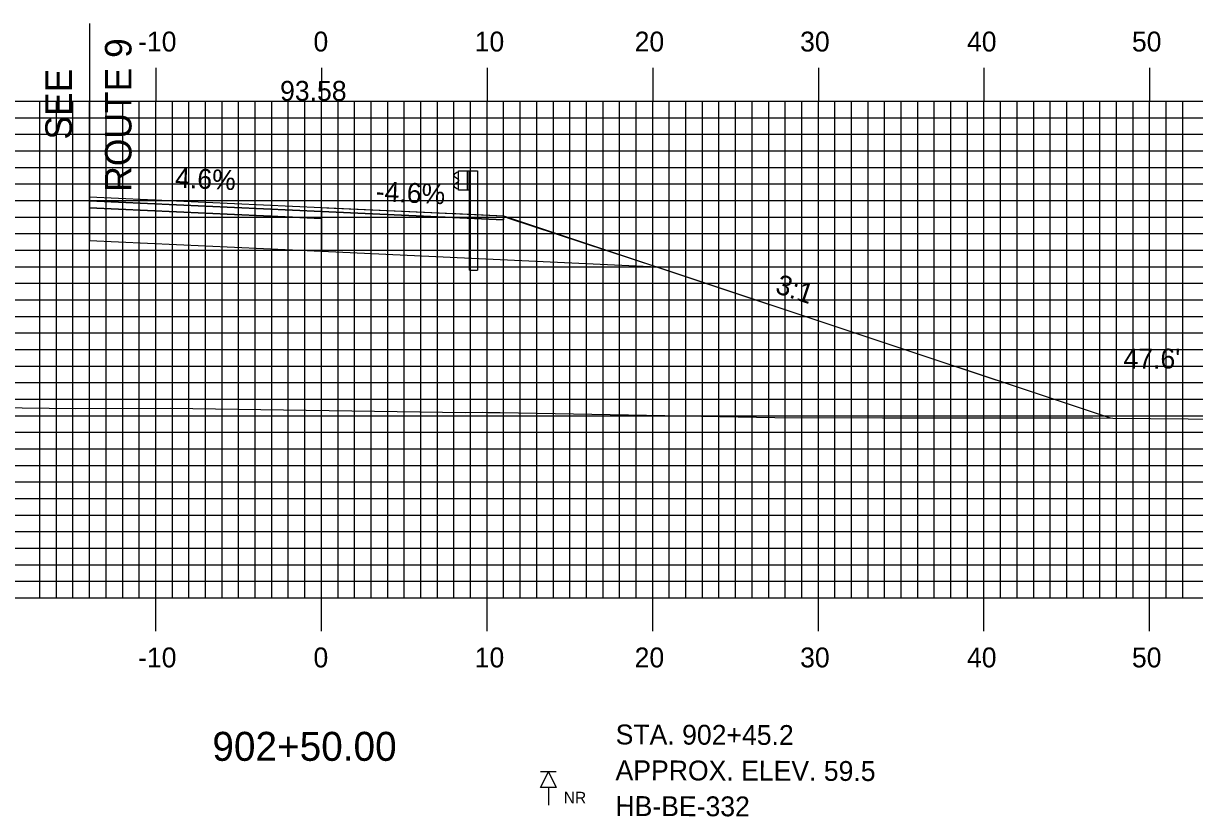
# Model space of a CAD drawing. Extents: x 856716 to 857060, y 364765 to 364985.
# Drawn here: x 856864.3 to 856935, y 364820.1 to 364868 of the extents above; entities that cross this region are included whole.
import ezdxf

# ---------------------------------------------------------------- set-up
doc = ezdxf.new("R2010")
doc.units = 0
for name, color, linetype in [('ANNOTATION', 7, 'Continuous'), ('BORING - NO REFUSAL', 7, 'Continuous'), ('D_Guardrail_Beam_Lt', 7, 'Continuous'), ('D_Roadway_Centerline', 7, 'Continuous'), ('D_Roadway_Centerline_Text', 7, 'Continuous'), ('D_Roadway_Edge_Shoulder', 7, 'Continuous'), ('D_Roadway_Edge_TW', 7, 'Continuous'), ('D_Roadway_Pavement', 7, 'Continuous'), ('D_Roadway_SlopeLines', 7, 'Continuous'), ('D_Roadway_SubGrade', 7, 'Continuous'), ('D_Text_Standard', 7, 'Continuous'), ('H_V ANNOTATION', 7, 'Continuous'), ('MAJOR', 7, 'Continuous'), ('MINOR', 7, 'Continuous'), ('S_Roadway_Centerline', 7, 'Continuous')]:
    doc.layers.add(name, color=color, linetype=linetype)

msp = doc.modelspace()

# ---------------------------------------------------------------- linework, layer by layer
at = {"layer": 'BORING - NO REFUSAL'}
for p, q in [((856896.461, 364822.802), (856895.502, 364822.802)), ((856895.981, 364821.843), (856895.981, 364820.784))]:
    msp.add_line(p, q, dxfattribs=at)
msp.add_lwpolyline([(856895.981, 364822.802), (856896.461, 364821.843), (856895.502, 364821.843)], close=True, dxfattribs=at)
at = {"layer": 'D_Guardrail_Beam_Lt'}
for p, q in [((856890.462, 364858.992), (856890.319, 364858.892)), ((856890.552, 364859.013), (856890.478, 364858.999)), ((856890.552, 364859.097), (856891.24, 364859.097)), ((856890.552, 364857.93), (856890.552, 364859.097)), ((856891.073, 364859.097), (856891.073, 364857.93)), ((856891.177, 364859.097), (856891.177, 364857.93)), ((856891.24, 364859.097), (856891.711, 364859.097)), ((856891.24, 364859.097), (856891.24, 364857.93)), ((856891.711, 364859.097), (856891.711, 364853.097)), ((856890.319, 364858.749), (856890.514, 364858.613)), ((856890.514, 364858.414), (856890.319, 364858.278)), ((856890.548, 364858.548), (856890.548, 364858.478)), ((856890.319, 364858.134), (856890.462, 364858.034)), ((856890.478, 364858.028), (856890.552, 364858.013)), ((856891.24, 364857.93), (856890.552, 364857.93)), ((856891.219, 364853.097), (856891.219, 364857.93)), ((856891.219, 364853.097), (856891.711, 364853.097))]:
    msp.add_line(p, q, dxfattribs=at)
for centre, major_axis, start_param, end_param in [((856890.486, 364858.958), (-0.0417, 0), 4.907132, 5.323254), ((856890.369, 364858.82), (-0.0877, 0), 5.323254, 7.243116), ((856890.369, 364858.206), (-0.0877, 0), 5.323254, 7.243116), ((856890.469, 364858.548), (0.0789, 0), 0, 0.959931), ((856890.469, 364858.478), (0.0789, 0), 5.323254, 6.283185), ((856890.486, 364858.068), (-0.0417, 0), 0.959931, 1.376053)]:
    msp.add_ellipse(centre, major_axis=major_axis, ratio=0.995501, start_param=start_param, end_param=end_param, dxfattribs=at)
at = {"layer": 'D_Roadway_Centerline'}
msp.add_lwpolyline([(856868.281, 364857.525), (856882.281, 364856.881), (856882.598, 364856.867), (856890.281, 364856.513), (856890.4, 364856.508), (856893.281, 364856.375), (856893.514, 364856.259), (856902.562, 364853.282), (856929.908, 364844.166)], dxfattribs=at)
at = {"layer": 'D_Roadway_Edge_Shoulder'}
for points in [[(856882.281, 364856.881), (856890.281, 364856.513), (856890.281, 364856.513), (856893.281, 364856.375), (856893.281, 364856.125), (856882.281, 364856.631)], [(856882.281, 364856.881), (856893.281, 364856.375), (856893.281, 364856.125), (856882.281, 364856.631)], [(856882.281, 364856.881), (856890.281, 364856.513), (856890.281, 364856.513), (856893.281, 364856.375), (856893.281, 364856.125), (856882.281, 364856.631)]]:
    msp.add_lwpolyline(points, close=True, dxfattribs=at)
at = {"layer": 'D_Roadway_Edge_TW'}
msp.add_lwpolyline([(856868.281, 364857.525), (856882.281, 364856.881), (856882.281, 364856.631), (856868.281, 364857.275)], close=True, dxfattribs=at)
msp.add_lwpolyline([(856868.281, 364857.525), (856882.281, 364856.881), (856882.281, 364856.631), (856868.281, 364857.275)], close=True, dxfattribs=at)
msp.add_lwpolyline([(856868.281, 364857.525), (856882.281, 364856.881), (856882.281, 364856.631), (856868.281, 364857.275)], close=True, dxfattribs=at)
msp.add_lwpolyline([(856868.281, 364857.525), (856868.281, 364857.275)], dxfattribs=at)
msp.add_lwpolyline([(856868.281, 364857.525), (856868.281, 364857.275)], dxfattribs=at)
at = {"layer": 'D_Roadway_Pavement'}
msp.add_lwpolyline([(856868.281, 364857.275), (856882.281, 364856.631), (856882.281, 364856.214), (856868.281, 364856.858)], close=True, dxfattribs=at)
msp.add_lwpolyline([(856868.281, 364857.275), (856882.281, 364856.631), (856882.281, 364856.214), (856868.281, 364856.858)], close=True, dxfattribs=at)
msp.add_lwpolyline([(856868.281, 364857.275), (856882.281, 364856.631), (856882.281, 364856.214), (856868.281, 364856.858)], close=True, dxfattribs=at)
msp.add_lwpolyline([(856868.281, 364857.275), (856882.281, 364856.631), (856882.281, 364856.214), (856868.281, 364856.858)], close=True, dxfattribs=at)
for points in [[(856868.281, 364857.275), (856868.281, 364856.858)], [(856868.281, 364857.275), (856868.281, 364856.858)], [(856868.281, 364857.275), (856868.281, 364856.858)], [(856868.281, 364857.275), (856868.281, 364856.858)], [(856882.281, 364856.631), (856882.281, 364856.214)], [(856882.281, 364856.631), (856882.281, 364856.214)], [(856882.281, 364856.631), (856882.281, 364856.214)], [(856882.281, 364856.631), (856882.281, 364856.214)], [(856882.281, 364856.631), (856882.281, 364856.214)], [(856882.281, 364856.631), (856882.281, 364856.214)], [(856882.281, 364856.631), (856882.281, 364856.214)], [(856882.281, 364856.631), (856882.281, 364856.214)]]:
    msp.add_lwpolyline(points, dxfattribs=at)
at = {"layer": 'D_Roadway_SlopeLines'}
msp.add_lwpolyline([(856893.281, 364856.375), (856929.908, 364844.166)], dxfattribs=at)
msp.add_lwpolyline([(856893.281, 364856.375), (856929.908, 364844.166)], dxfattribs=at)
msp.add_lwpolyline([(856893.281, 364856.375), (856929.908, 364844.166)], dxfattribs=at)
msp.add_lwpolyline([(856893.281, 364856.375), (856929.908, 364844.166)], dxfattribs=at)
msp.add_lwpolyline([(856893.281, 364856.375), (856929.908, 364844.166)], dxfattribs=at)
at = {"layer": 'D_Roadway_SubGrade'}
msp.add_line((856868.281, 364867.998), (856868.281, 364854.858), dxfattribs=at)
for points in [[(856868.281, 364856.858), (856882.281, 364856.214), (856882.281, 364854.214), (856868.281, 364854.858)], [(856868.281, 364856.858), (856882.281, 364856.214), (856882.281, 364854.214), (856868.281, 364854.858)], [(856882.281, 364856.214), (856882.281, 364856.631), (856893.281, 364856.125), (856893.281, 364856.375), (856902.562, 364853.282), (856882.281, 364854.214)]]:
    msp.add_lwpolyline(points, close=True, dxfattribs=at)
msp.add_lwpolyline([(856868.281, 364856.858), (856868.281, 364854.858)], dxfattribs=at)
msp.add_lwpolyline([(856868.281, 364856.858), (856868.281, 364854.858)], dxfattribs=at)
at = {"layer": 'MAJOR'}
for p, q in [((856872.281, 364865.306), (856872.281, 364863.302)), ((856882.281, 364865.306), (856882.281, 364863.302)), ((856892.281, 364865.306), (856892.281, 364863.302)), ((856902.281, 364865.306), (856902.281, 364863.302)), ((856912.281, 364865.306), (856912.281, 364863.302)), ((856922.281, 364865.306), (856922.281, 364863.302)), ((856932.281, 364865.306), (856932.281, 364863.302)), ((856742.281, 364863.302), (857022.281, 364863.302)), ((856742.281, 364863.302), (857022.281, 364863.302)), ((856872.281, 364833.302), (856872.281, 364863.302)), ((856882.281, 364833.302), (856882.281, 364863.302)), ((856892.281, 364833.302), (856892.281, 364863.302)), ((856902.281, 364833.302), (856902.281, 364863.302)), ((856912.281, 364833.302), (856912.281, 364863.302)), ((856922.281, 364833.302), (856922.281, 364863.302)), ((856932.281, 364833.302), (856932.281, 364863.302)), ((856742.281, 364858.302), (857022.281, 364858.302)), ((856742.281, 364853.302), (857022.281, 364853.302)), ((856742.281, 364848.302), (857022.281, 364848.302)), ((856742.281, 364843.302), (857022.281, 364843.302)), ((856742.281, 364838.302), (857022.281, 364838.302)), ((856742.281, 364833.302), (857022.281, 364833.302)), ((856742.281, 364833.302), (857022.281, 364833.302)), ((856872.281, 364831.298), (856872.281, 364833.302)), ((856882.281, 364831.298), (856882.281, 364833.302)), ((856892.281, 364831.298), (856892.281, 364833.302)), ((856902.281, 364831.298), (856902.281, 364833.302)), ((856912.281, 364831.298), (856912.281, 364833.302)), ((856922.281, 364831.298), (856922.281, 364833.302)), ((856932.281, 364831.298), (856932.281, 364833.302))]:
    msp.add_line(p, q, dxfattribs=at)
at = {"layer": 'MINOR'}
for p, q in [((856865.281, 364833.302), (856865.281, 364863.302)), ((856866.281, 364833.302), (856866.281, 364863.302)), ((856867.281, 364833.302), (856867.281, 364863.302)), ((856868.281, 364833.302), (856868.281, 364863.302)), ((856869.281, 364833.302), (856869.281, 364863.302)), ((856870.281, 364833.302), (856870.281, 364863.302)), ((856871.281, 364833.302), (856871.281, 364863.302)), ((856873.281, 364833.302), (856873.281, 364863.302)), ((856874.281, 364833.302), (856874.281, 364863.302)), ((856875.281, 364833.302), (856875.281, 364863.302)), ((856876.281, 364833.302), (856876.281, 364863.302)), ((856877.281, 364833.302), (856877.281, 364863.302)), ((856878.281, 364833.302), (856878.281, 364863.302)), ((856879.281, 364833.302), (856879.281, 364863.302)), ((856880.281, 364833.302), (856880.281, 364863.302)), ((856881.281, 364833.302), (856881.281, 364863.302)), ((856883.281, 364833.302), (856883.281, 364863.302)), ((856884.281, 364833.302), (856884.281, 364863.302)), ((856885.281, 364833.302), (856885.281, 364863.302)), ((856886.281, 364833.302), (856886.281, 364863.302)), ((856887.281, 364833.302), (856887.281, 364863.302)), ((856888.281, 364833.302), (856888.281, 364863.302)), ((856889.281, 364833.302), (856889.281, 364863.302)), ((856890.281, 364833.302), (856890.281, 364863.302)), ((856891.281, 364833.302), (856891.281, 364863.302)), ((856893.281, 364833.302), (856893.281, 364863.302)), ((856894.281, 364833.302), (856894.281, 364863.302)), ((856895.281, 364833.302), (856895.281, 364863.302)), ((856896.281, 364833.302), (856896.281, 364863.302)), ((856897.281, 364833.302), (856897.281, 364863.302)), ((856898.281, 364833.302), (856898.281, 364863.302)), ((856899.281, 364833.302), (856899.281, 364863.302)), ((856900.281, 364833.302), (856900.281, 364863.302)), ((856901.281, 364833.302), (856901.281, 364863.302)), ((856903.281, 364833.302), (856903.281, 364863.302)), ((856904.281, 364833.302), (856904.281, 364863.302)), ((856905.281, 364833.302), (856905.281, 364863.302)), ((856906.281, 364833.302), (856906.281, 364863.302)), ((856907.281, 364833.302), (856907.281, 364863.302)), ((856908.281, 364833.302), (856908.281, 364863.302)), ((856909.281, 364833.302), (856909.281, 364863.302)), ((856910.281, 364833.302), (856910.281, 364863.302)), ((856911.281, 364833.302), (856911.281, 364863.302)), ((856913.281, 364833.302), (856913.281, 364863.302)), ((856914.281, 364833.302), (856914.281, 364863.302)), ((856915.281, 364833.302), (856915.281, 364863.302)), ((856916.281, 364833.302), (856916.281, 364863.302)), ((856917.281, 364833.302), (856917.281, 364863.302)), ((856918.281, 364833.302), (856918.281, 364863.302)), ((856919.281, 364833.302), (856919.281, 364863.302)), ((856920.281, 364833.302), (856920.281, 364863.302)), ((856921.281, 364833.302), (856921.281, 364863.302)), ((856923.281, 364833.302), (856923.281, 364863.302)), ((856924.281, 364833.302), (856924.281, 364863.302)), ((856925.281, 364833.302), (856925.281, 364863.302)), ((856926.281, 364833.302), (856926.281, 364863.302)), ((856927.281, 364833.302), (856927.281, 364863.302)), ((856928.281, 364833.302), (856928.281, 364863.302)), ((856929.281, 364833.302), (856929.281, 364863.302)), ((856930.281, 364833.302), (856930.281, 364863.302)), ((856931.281, 364833.302), (856931.281, 364863.302)), ((856933.281, 364833.302), (856933.281, 364863.302)), ((856934.281, 364833.302), (856934.281, 364863.302)), ((856742.281, 364862.302), (857022.281, 364862.302)), ((856742.281, 364861.302), (857022.281, 364861.302)), ((856742.281, 364860.302), (857022.281, 364860.302)), ((856742.281, 364859.302), (857022.281, 364859.302)), ((856742.281, 364857.302), (857022.281, 364857.302)), ((856742.281, 364856.302), (857022.281, 364856.302)), ((856742.281, 364855.302), (857022.281, 364855.302)), ((856742.281, 364854.302), (857022.281, 364854.302)), ((856742.281, 364852.302), (857022.281, 364852.302)), ((856742.281, 364851.302), (857022.281, 364851.302)), ((856742.281, 364850.302), (857022.281, 364850.302)), ((856742.281, 364849.302), (857022.281, 364849.302)), ((856742.281, 364847.302), (857022.281, 364847.302)), ((856742.281, 364846.302), (857022.281, 364846.302)), ((856742.281, 364845.302), (857022.281, 364845.302)), ((856742.281, 364844.302), (857022.281, 364844.302)), ((856742.281, 364842.302), (857022.281, 364842.302)), ((856742.281, 364841.302), (857022.281, 364841.302)), ((856742.281, 364840.302), (857022.281, 364840.302)), ((856742.281, 364839.302), (857022.281, 364839.302)), ((856742.281, 364837.302), (857022.281, 364837.302)), ((856742.281, 364836.302), (857022.281, 364836.302)), ((856742.281, 364835.302), (857022.281, 364835.302)), ((856742.281, 364834.302), (857022.281, 364834.302))]:
    msp.add_line(p, q, dxfattribs=at)
at = {"layer": 'S_Roadway_Centerline'}
msp.add_lwpolyline([(856856.1, 364844.883), (856867.463, 364844.742), (856873.147, 364844.764), (856890.95, 364844.505), (856892.034, 364844.51), (856892.346, 364844.506), (856893.067, 364844.491), (856909.644, 364844.197), (856916.162, 364844.178), (856928.478, 364844.179), (856928.843, 364844.18), (856930.057, 364844.165), (856941.408, 364844.057), (856947.015, 364844.149), (856963.638, 364844.114), (856965.102, 364844.126), (856965.611, 364844.134), (856966.715, 364844.134), (856978.087, 364844.109), (856983.507, 364844.216)], dxfattribs=at)

# ---------------------------------------------------------------- texts
at = {"layer": 'ANNOTATION'}
for s, height, rotation, p in [('ROUTE 9', 1.6, 90, (856870.813, 364857.831)), ('SEE', 1.6, 90, (856867.213, 364860.981)), ('4.6%', 1.2, 357.36625, (856873.428, 364858.091)), ('-4.6%', 1.2, 357.36625, (856885.54, 364857.266)), ('3:1', 1.2, 341.56505, (856909.618, 364851.739))]:
    msp.add_text(s, height=height, rotation=rotation, dxfattribs=at).set_placement(p)
at = {"layer": 'BORING - NO REFUSAL'}
for s, p in [('STA. 902+45.2', (856900.042, 364824.45)), ('APPROX. ELEV. 59.5', (856900.035, 364822.29)), ('HB-BE-332', (856900.028, 364820.13))]:
    msp.add_text(s, height=1.2, rotation=359.81416, dxfattribs=at).set_placement(p)
msp.add_text('NR', height=0.6998, dxfattribs=at).set_placement((856896.914, 364820.887))
at = {"layer": 'D_Roadway_Centerline_Text'}
msp.add_text('93.58', height=1.2, dxfattribs=at).set_placement((856879.783, 364863.325))
at = {"layer": 'D_Text_Standard'}
msp.add_text("47.6'", height=1.2, dxfattribs=at).set_placement((856930.703, 364847.154))
at = {"layer": 'H_V ANNOTATION'}
for s, height, p in [('-10', 1.2, (856871.211, 364866.302)), ('0', 1.2, (856881.8, 364866.302)), ('10', 1.2, (856891.532, 364866.302)), ('20', 1.2, (856901.189, 364866.302)), ('30', 1.2, (856911.179, 364866.302)), ('40', 1.2, (856921.254, 364866.302)), ('50', 1.2, (856931.211, 364866.302)), ('-10', 1.2, (856871.211, 364829.102)), ('0', 1.2, (856881.8, 364829.102)), ('10', 1.2, (856891.532, 364829.102)), ('20', 1.2, (856901.189, 364829.102)), ('30', 1.2, (856911.179, 364829.102)), ('40', 1.2, (856921.254, 364829.102)), ('50', 1.2, (856931.211, 364829.102)), ('902+50.00', 1.75, (856875.695, 364823.458))]:
    msp.add_text(s, height=height, dxfattribs=at).set_placement(p)

doc.saveas('drawing.dxf')
